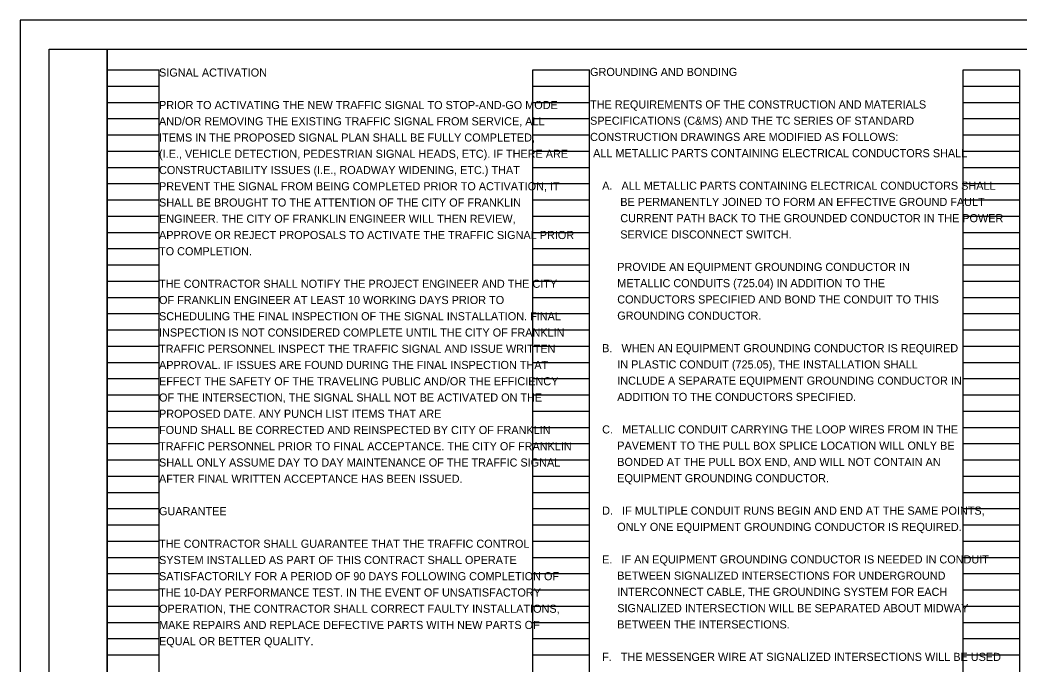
# Model space of a CAD drawing. Extents: x 0 to 34, y 0 to 22.
# Drawn here: x 0 to 17.24, y 10.89 to 22 of the extents above; entities that cross this region are included whole.
import ezdxf

# ---------------------------------------------------------------- set-up
doc = ezdxf.new("R2010")
doc.units = 0
for name, color, linetype in [('SH_Border', 7, 'Continuous'), ('SH_Cut_Line', 7, 'Continuous'), ('SH_Data', 7, 'Continuous'), ('SH_Text', 7, 'Continuous')]:
    doc.layers.add(name, color=color, linetype=linetype)

msp = doc.modelspace()

# ---------------------------------------------------------------- linework, layer by layer
at = {"layer": 'SH_Border'}
for points in [[(0.5, 21.5), (1.5, 21.5), (1.5, 0.5), (0.5, 0.5)], [(1.5, 21.5), (33.5, 21.5), (33.5, 0.5), (1.5, 0.5)]]:
    msp.add_lwpolyline(points, close=True, dxfattribs=at)
at = {"layer": 'SH_Cut_Line'}
msp.add_lwpolyline([(0, 0), (34, 0), (34, 22), (0, 22)], close=True, dxfattribs=at)
at = {"layer": 'SH_Data'}
for p, q in [((1.5, 0.98), (1.5, 21.14)), ((1.5, 21.14), (2.4, 21.14)), ((2.4, 0.98), (2.4, 21.14)), ((8.84, 0.98), (8.84, 21.14)), ((8.84, 21.14), (9.82, 21.14)), ((9.82, 0.98), (9.82, 21.14)), ((16.26, 0.98), (16.26, 21.14)), ((16.26, 21.14), (17.24, 21.14)), ((17.24, 0.98), (17.24, 21.14)), ((1.5, 20.86), (2.4, 20.86)), ((8.84, 20.86), (9.82, 20.86)), ((16.26, 20.86), (17.24, 20.86)), ((1.5, 20.58), (2.4, 20.58)), ((8.84, 20.58), (9.82, 20.58)), ((16.26, 20.58), (17.24, 20.58)), ((1.5, 20.3), (2.4, 20.3)), ((8.84, 20.3), (9.82, 20.3)), ((16.26, 20.3), (17.24, 20.3)), ((1.5, 20.02), (2.4, 20.02)), ((8.84, 20.02), (9.82, 20.02)), ((16.26, 20.02), (17.24, 20.02)), ((1.5, 19.74), (2.4, 19.74)), ((8.84, 19.74), (9.82, 19.74)), ((16.26, 19.74), (17.24, 19.74)), ((1.5, 19.46), (2.4, 19.46)), ((8.84, 19.46), (9.82, 19.46)), ((16.26, 19.46), (17.24, 19.46)), ((1.5, 19.18), (2.4, 19.18)), ((8.84, 19.18), (9.82, 19.18)), ((16.26, 19.18), (17.24, 19.18)), ((1.5, 18.9), (2.4, 18.9)), ((8.84, 18.9), (9.82, 18.9)), ((16.26, 18.9), (17.24, 18.9)), ((1.5, 18.62), (2.4, 18.62)), ((8.84, 18.62), (9.82, 18.62)), ((16.26, 18.62), (17.24, 18.62)), ((1.5, 18.34), (2.4, 18.34)), ((8.84, 18.34), (9.82, 18.34)), ((16.26, 18.34), (17.24, 18.34)), ((1.5, 18.06), (2.4, 18.06)), ((8.84, 18.06), (9.82, 18.06)), ((16.26, 18.06), (17.24, 18.06)), ((1.5, 17.78), (2.4, 17.78)), ((8.84, 17.78), (9.82, 17.78)), ((16.26, 17.78), (17.24, 17.78)), ((1.5, 17.5), (2.4, 17.5)), ((8.84, 17.5), (9.82, 17.5)), ((16.26, 17.5), (17.24, 17.5)), ((1.5, 17.22), (2.4, 17.22)), ((8.84, 17.22), (9.82, 17.22)), ((16.26, 17.22), (17.24, 17.22)), ((1.5, 16.94), (2.4, 16.94)), ((8.84, 16.94), (9.82, 16.94)), ((16.26, 16.94), (17.24, 16.94)), ((1.5, 16.66), (2.4, 16.66)), ((8.84, 16.66), (9.82, 16.66)), ((16.26, 16.66), (17.24, 16.66)), ((1.5, 16.38), (2.4, 16.38)), ((8.84, 16.38), (9.82, 16.38)), ((16.26, 16.38), (17.24, 16.38)), ((1.5, 16.1), (2.4, 16.1)), ((8.84, 16.1), (9.82, 16.1)), ((16.26, 16.1), (17.24, 16.1)), ((1.5, 15.82), (2.4, 15.82)), ((8.84, 15.82), (9.82, 15.82)), ((16.26, 15.82), (17.24, 15.82)), ((1.5, 15.54), (2.4, 15.54)), ((8.84, 15.54), (9.82, 15.54)), ((16.26, 15.54), (17.24, 15.54)), ((1.5, 15.26), (2.4, 15.26)), ((8.84, 15.26), (9.82, 15.26)), ((16.26, 15.26), (17.24, 15.26)), ((1.5, 14.98), (2.4, 14.98)), ((8.84, 14.98), (9.82, 14.98)), ((16.26, 14.98), (17.24, 14.98)), ((1.5, 14.7), (2.4, 14.7)), ((8.84, 14.7), (9.82, 14.7)), ((16.26, 14.7), (17.24, 14.7)), ((1.5, 14.42), (2.4, 14.42)), ((8.84, 14.42), (9.82, 14.42)), ((16.26, 14.42), (17.24, 14.42)), ((1.5, 14.14), (2.4, 14.14)), ((8.84, 14.14), (9.82, 14.14)), ((16.26, 14.14), (17.24, 14.14)), ((1.5, 13.86), (2.4, 13.86)), ((8.84, 13.86), (9.82, 13.86)), ((16.26, 13.86), (17.24, 13.86)), ((1.5, 13.58), (2.4, 13.58)), ((8.84, 13.58), (9.82, 13.58)), ((16.26, 13.58), (17.24, 13.58)), ((1.5, 13.3), (2.4, 13.3)), ((8.84, 13.3), (9.82, 13.3)), ((16.26, 13.3), (17.24, 13.3)), ((1.5, 13.02), (2.4, 13.02)), ((8.84, 13.02), (9.82, 13.02)), ((16.26, 13.02), (17.24, 13.02)), ((1.5, 12.74), (2.4, 12.74)), ((8.84, 12.74), (9.82, 12.74)), ((16.26, 12.74), (17.24, 12.74)), ((1.5, 12.46), (2.4, 12.46)), ((8.84, 12.46), (9.82, 12.46)), ((16.26, 12.46), (17.24, 12.46)), ((1.5, 12.18), (2.4, 12.18)), ((8.84, 12.18), (9.82, 12.18)), ((16.26, 12.18), (17.24, 12.18)), ((1.5, 11.9), (2.4, 11.9)), ((8.84, 11.9), (9.82, 11.9)), ((16.26, 11.9), (17.24, 11.9)), ((1.5, 11.62), (2.4, 11.62)), ((8.84, 11.62), (9.82, 11.62)), ((16.26, 11.62), (17.24, 11.62)), ((1.5, 11.34), (2.4, 11.34)), ((8.84, 11.34), (9.82, 11.34)), ((16.26, 11.34), (17.24, 11.34)), ((1.5, 11.06), (2.4, 11.06)), ((8.84, 11.06), (9.82, 11.06)), ((16.26, 11.06), (17.24, 11.06))]:
    msp.add_line(p, q, dxfattribs=at)

# ---------------------------------------------------------------- texts
at = {"layer": 'SH_Text'}
for s, p in [('SIGNAL ACTIVATION', (2.397, 21.025)), ('GROUNDING AND BONDING', (9.829, 21.035)), ('PRIOR TO ACTIVATING THE NEW TRAFFIC SIGNAL TO STOP-AND-GO MODE ', (2.397, 20.465)), ('THE REQUIREMENTS OF THE CONSTRUCTION AND MATERIALS ', (9.829, 20.475)), ('AND/OR REMOVING THE EXISTING TRAFFIC SIGNAL FROM SERVICE, ALL ', (2.397, 20.185)), ('SPECIFICATIONS (C&MS) AND THE TC SERIES OF STANDARD', (9.829, 20.195)), ('ITEMS IN THE PROPOSED SIGNAL PLAN SHALL BE FULLY COMPLETED,', (2.397, 19.905)), ('CONSTRUCTION DRAWINGS ARE MODIFIED AS FOLLOWS:', (9.829, 19.915)), ('(I.E., VEHICLE DETECTION, PEDESTRIAN SIGNAL HEADS, ETC). IF THERE ARE ', (2.397, 19.625)), (' ALL METALLIC PARTS CONTAINING ELECTRICAL CONDUCTORS SHALL', (9.829, 19.635)), ('CONSTRUCTABILITY ISSUES (I.E., ROADWAY WIDENING, ETC.) THAT ', (2.397, 19.345)), ('PREVENT THE SIGNAL FROM BEING COMPLETED PRIOR TO ACTIVATION, IT ', (2.397, 19.065)), ('    A.   ALL METALLIC PARTS CONTAINING ELECTRICAL CONDUCTORS SHALL', (9.829, 19.075)), ('SHALL BE BROUGHT TO THE ATTENTION OF THE CITY OF FRANKLIN ', (2.397, 18.785)), ('          BE PERMANENTLY JOINED TO FORM AN EFFECTIVE GROUND FAULT', (9.829, 18.795)), ('ENGINEER. THE CITY OF FRANKLIN ENGINEER WILL THEN REVIEW, ', (2.397, 18.505)), ('          CURRENT PATH BACK TO THE GROUNDED CONDUCTOR IN THE POWER ', (9.829, 18.515)), ('APPROVE OR REJECT PROPOSALS TO ACTIVATE THE TRAFFIC SIGNAL PRIOR ', (2.397, 18.225)), ('          SERVICE DISCONNECT SWITCH.', (9.829, 18.235)), ('TO COMPLETION.', (2.397, 17.945)), ('         PROVIDE AN EQUIPMENT GROUNDING CONDUCTOR IN', (9.829, 17.675)), ('THE CONTRACTOR SHALL NOTIFY THE PROJECT ENGINEER AND THE CITY ', (2.397, 17.385)), ('         METALLIC CONDUITS (725.04) IN ADDITION TO THE', (9.829, 17.395)), ('OF FRANKLIN ENGINEER AT LEAST 10 WORKING DAYS PRIOR TO ', (2.397, 17.105)), ('         CONDUCTORS SPECIFIED AND BOND THE CONDUIT TO THIS', (9.829, 17.115)), ('SCHEDULING THE FINAL INSPECTION OF THE SIGNAL INSTALLATION. FINAL ', (2.397, 16.825)), ('         GROUNDING CONDUCTOR.', (9.829, 16.835)), ('INSPECTION IS NOT CONSIDERED COMPLETE UNTIL THE CITY OF FRANKLIN ', (2.397, 16.545)), ('TRAFFIC PERSONNEL INSPECT THE TRAFFIC SIGNAL AND ISSUE WRITTEN ', (2.397, 16.265)), ('    B.   WHEN AN EQUIPMENT GROUNDING CONDUCTOR IS REQUIRED', (9.829, 16.275)), ('APPROVAL. IF ISSUES ARE FOUND DURING THE FINAL INSPECTION THAT ', (2.397, 15.985)), ('         IN PLASTIC CONDUIT (725.05), THE INSTALLATION SHALL', (9.829, 15.995)), ('EFFECT THE SAFETY OF THE TRAVELING PUBLIC AND/OR THE EFFICIENCY ', (2.397, 15.705)), ('         INCLUDE A SEPARATE EQUIPMENT GROUNDING CONDUCTOR IN', (9.829, 15.715)), ('OF THE INTERSECTION, THE SIGNAL SHALL NOT BE ACTIVATED ON THE ', (2.397, 15.425)), ('         ADDITION TO THE CONDUCTORS SPECIFIED.', (9.829, 15.435)), ('PROPOSED DATE. ANY PUNCH LIST ITEMS THAT ARE', (2.397, 15.145)), ('FOUND SHALL BE CORRECTED AND REINSPECTED BY CITY OF FRANKLIN', (2.397, 14.865)), ('    C.   METALLIC CONDUIT CARRYING THE LOOP WIRES FROM IN THE', (9.829, 14.875)), ('TRAFFIC PERSONNEL PRIOR TO FINAL ACCEPTANCE. THE CITY OF FRANKLIN ', (2.397, 14.585)), ('         PAVEMENT TO THE PULL BOX SPLICE LOCATION WILL ONLY BE', (9.829, 14.595)), ('SHALL ONLY ASSUME DAY TO DAY MAINTENANCE OF THE TRAFFIC SIGNAL ', (2.397, 14.305)), ('         BONDED AT THE PULL BOX END, AND WILL NOT CONTAIN AN', (9.829, 14.315)), ('AFTER FINAL WRITTEN ACCEPTANCE HAS BEEN ISSUED.', (2.397, 14.025)), ('         EQUIPMENT GROUNDING CONDUCTOR.', (9.829, 14.035)), ('GUARANTEE', (2.397, 13.465)), ('    D.   IF MULTIPLE CONDUIT RUNS BEGIN AND END AT THE SAME POINTS,', (9.829, 13.475)), ('         ONLY ONE EQUIPMENT GROUNDING CONDUCTOR IS REQUIRED.', (9.829, 13.195)), ('THE CONTRACTOR SHALL GUARANTEE THAT THE TRAFFIC CONTROL ', (2.397, 12.905)), ('SYSTEM INSTALLED AS PART OF THIS CONTRACT SHALL OPERATE ', (2.397, 12.625)), ('    E.   IF AN EQUIPMENT GROUNDING CONDUCTOR IS NEEDED IN CONDUIT', (9.829, 12.635)), ('SATISFACTORILY FOR A PERIOD OF 90 DAYS FOLLOWING COMPLETION OF ', (2.397, 12.345)), ('         BETWEEN SIGNALIZED INTERSECTIONS FOR UNDERGROUND', (9.829, 12.355)), ('THE 10-DAY PERFORMANCE TEST. IN THE EVENT OF UNSATISFACTORY ', (2.397, 12.065)), ('         INTERCONNECT CABLE, THE GROUNDING SYSTEM FOR EACH ', (9.829, 12.075)), ('OPERATION, THE CONTRACTOR SHALL CORRECT FAULTY INSTALLATIONS, ', (2.397, 11.785)), ('         SIGNALIZED INTERSECTION WILL BE SEPARATED ABOUT MIDWAY', (9.829, 11.795)), ('MAKE REPAIRS AND REPLACE DEFECTIVE PARTS WITH NEW PARTS OF', (2.397, 11.505)), ('         BETWEEN THE INTERSECTIONS.', (9.829, 11.515)), ('EQUAL OR BETTER QUALITY.', (2.397, 11.225)), ('    F.   THE MESSENGER WIRE AT SIGNALIZED INTERSECTIONS WILL BE USED', (9.829, 10.955))]:
    msp.add_text(s, height=0.14, dxfattribs=at).set_placement(p)

doc.saveas('drawing.dxf')
